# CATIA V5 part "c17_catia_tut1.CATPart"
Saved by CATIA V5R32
Part number: Part1
Bounding box of the stored display mesh (mm): x 0 to 100, y -49.812 to 49.812, z 0 to 49.812
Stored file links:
  D:\PROJECTS\Project 2022\CATIA V5 6R 2022\Resources\Tutorial Files\c17_catia_v5_6r2022_tut\c17_catia_tut1.CATPart
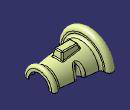
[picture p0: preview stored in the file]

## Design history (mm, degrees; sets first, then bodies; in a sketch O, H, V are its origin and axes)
Body1 (main body)
  Sketch1 on xy-plane, origin (0, 0, 0), H (1, 0, 0), V (0, 1, 0)
    point P1 (0, 30)
    line L1 (0, 30) -> (0, 42.5)
    arc A1 centre (7.5, 42.5) radius 7.5 from (0, 42.5) to (15, 42.5) cw
    point P3 (7.5, 42.5)
    line L2 (15, 42.5) -> (15, 35)
    point P5 (15, 35)
    line L3 (15, 35) -> (90.101, 24)
    point P6 (90.101, 24)
    arc A2 centre (95, 25) radius 5 from (90.101, 24) to (100, 25) cw
    point P7 (95, 25)
    line L4 (100, 25) -> (100, 20)
    point P9 (100, 20)
    axis line L5 (0, 0) -> (130.0291, 0)
    radius A1 = 7.5
    distance L1 L4 = 100
    radius A2 = 5
    radius about axis P1 L5 = 30
    radius about axis P3 L5 = 42.5
    radius about axis P5 L5 = 35
    radius about axis P9 L5 = 20
    radius about axis P7 L5 = 25
    radius about axis P6 L5 = 24
    coincidence: P1 V
    tangency: A1 L1, L2 A1, L4 A2
    vertical: L1 V, L2 V, L4 V
    horizontal: L5 H
  Revol1: Element1 Sketch1, Angle1 180
  Sketch2 on xy-plane, origin (0, 0, 0), H (1, 0, 0), V (0, 1, 0)
    point P1 (50, 29.8736)
    ellipse A1 centre (50, 29.8736) semi-axes 10, 5 rotation 90
    reference projected line E1 (90.101, 24) -> (15, 35) from Sketch1.L3
    reference projected point E2 (100, 20) from Sketch1.P9
    ellipse A2 centre (50, -29.8736) semi-axes 10, 5 rotation 270
    "Radius" A1 = 10
    "Radius" A1 = 5
    distance P1 E2 H = 50
    vertical: A1 V
    coincidence: P1 E1
    symmetry: A1 A2 H
  Extrude1: Element1 Sketch2, Lim1 40, Lim2 0, Direction xy-plane
  Trim1: Trimmed (Revol1; Extrude1)
  Fillet1: radius 5, on edge [face of Revol1 from Sketch1.L3 | face of Extrude1 from Sketch2.A2]; edge [face of Revol1 from Sketch1.L3 | face of Extrude1 from Sketch2.A1]
  Plane1: type Offset, RefPlane xy-plane, Offset 40
  Sketch3 on Plane1, origin (0, 0, 40), H (1, 0, 0), V (0, 1, 0)
    line L1 (30, 10) -> (65, 10)
    line L2 (65, 10) -> (65, -10)
    line L3 (65, -10) -> (30, -10)
    line L4 (30, -10) -> (30, 10)
    reference projected line E1 (100, 25) -> (100, -25) from edge [face of Revol1 from Sketch1.L4 | face of Revol1 from Sketch1.A2]
    distance L2 E1 = 35
    length L1 = 35
    length L2 = 20
    horizontal: L1 H, L3 H
    vertical: L2 V, L4 V
    symmetry: L1 L3 H
  Project1: ToProject Sketch3, Support Fillet1, Direction xy-plane
  Sketch4 on Plane1, origin (0, 0, 40), H (1, 0, 0), V (0, 1, 0)
    line L1 (32.5, 7.5) -> (62.5, 7.5)
    line L2 (62.5, 7.5) -> (62.5, -7.5)
    line L3 (62.5, -7.5) -> (32.5, -7.5)
    line L4 (32.5, -7.5) -> (32.5, 7.5)
    reference projected line E1 (100, 25) -> (100, -25) from edge [face of Revol1 from Sketch1.L4 | face of Revol1 from Sketch1.A2]
    distance L2 E1 = 37.5
    length L1 = 30
    length L2 = 15
    horizontal: L1 H, L3 H
    vertical: L2 V, L4 V
    symmetry: L3 L1 H
  Loft1: Sections (Project1; Sketch4), SectionCouplingPoints ({coupling CouplingPoints (vertex [face of Project1 | face of Project1]; vertex [element of Sketch4 | element of Sketch4])}; {coupling CouplingPoints (vertex [face of Project1 | face of Project1]; vertex [element of Sketch4 | element of Sketch4])}; {coupling CouplingPoints (vertex [face of Project1 | face of Project1]; vertex [element of Sketch4 | element of Sketch4])})
  Trim2: Trimmed (Loft1; Fillet1)
  Fill1: Boundary (edge of Loft1; edge of Loft1; edge of Loft1; edge of Loft1)
  Join1: Elements (Trim2; Fill1)
  Fillet2: radius 5, on edge [face of Revol1 from Sketch1.L3 | face of Revol1 from Sketch1.L2]; edge [face of Revol1 from Sketch1.A2 | face of Revol1 from Sketch1.L3]
  Fillet3: radius 2, on face of Fill1; edge [face of Loft1 | face of Loft1]; face of Loft1 (x4)
  Set1
    ThickSurface1: BotOffset 0, Surface Fillet3, TopOffset 1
